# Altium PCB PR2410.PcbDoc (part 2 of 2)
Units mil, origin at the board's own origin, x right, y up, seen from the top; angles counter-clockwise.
Board outline 2750 x 3900 mil, 2 copper layers (Top Layer, Bottom Layer), stack 61.6 mil thick; 140 components, 78 nets, 324 pads, 132 vias.
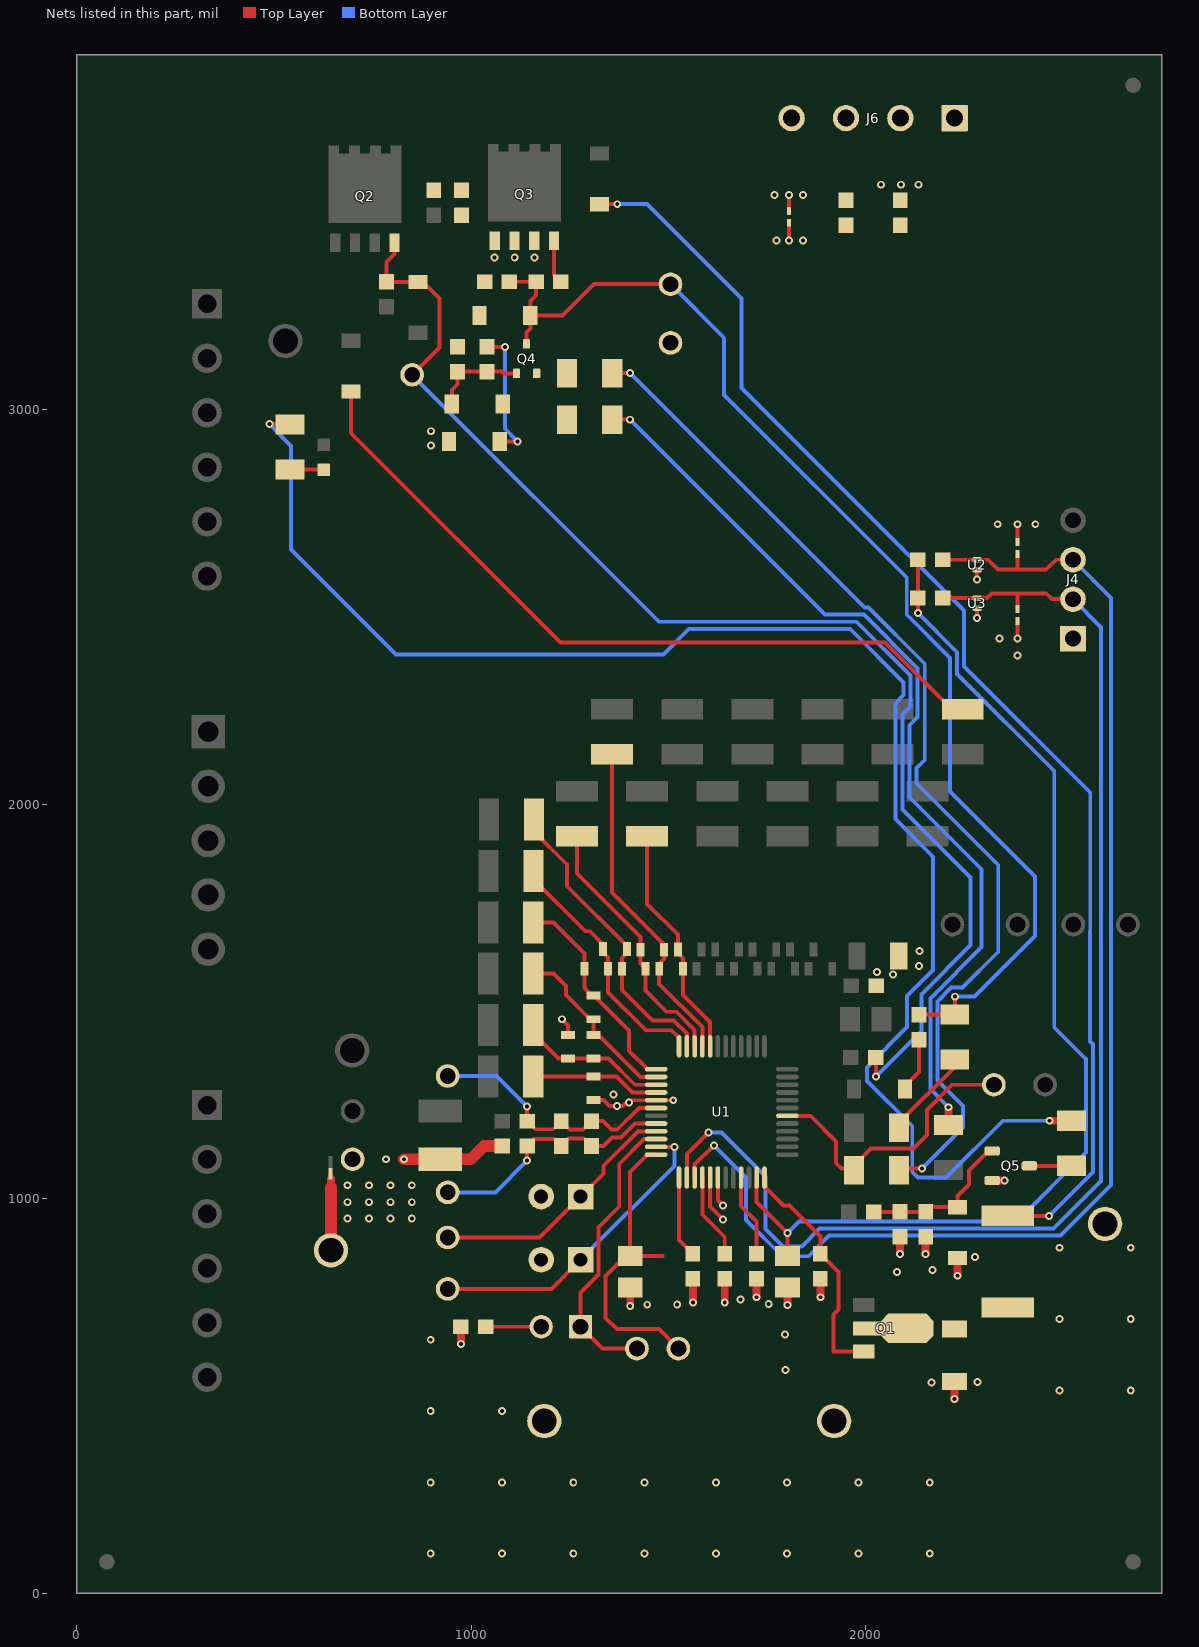
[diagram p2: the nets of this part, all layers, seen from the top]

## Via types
v1: diameter 20, hole 10, Top Layer to Bottom Layer, tented top, 132 vias

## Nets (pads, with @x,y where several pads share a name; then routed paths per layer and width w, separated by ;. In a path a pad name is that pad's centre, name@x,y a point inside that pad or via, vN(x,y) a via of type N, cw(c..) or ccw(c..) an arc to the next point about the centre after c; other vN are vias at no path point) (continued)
NetC11_2: C11.2 C12.1 R11.2 U1.8 | length 598.8
  Top Layer w10: R11.2@1445.82,1919 1445.82,1747.18 1523.67,1669.33 C11.2@1523.67,1632.08 1523.67,1622.33 1536.33,1609.67 C12.1@1536.33,1583.08 1536.33,1516.67 1605.47,1447.53 U1.8@1605.47,1386.34
NetC12_2: C12.2 C14.1 R12.2 U1.9 | length 846
  Top Layer w10: R12.2@1356.91,2127 1356.91,1776.09 1489,1644 C14.1@1489,1631.08 1489,1608 1476.33,1595.33 C12.2@1476.33,1583.08 1476.33,1544.56 1585.79,1435.11 U1.9@1585.79,1386.34
NetC13_1: C13.1 Q1.2 Q1.4 R9.1
NetC14_2: C14.2 C17.1 R13.2 U1.10 | length 670.8
  Top Layer w10: R13.2@1268,1919 1268,1824 1429,1663 C14.2@1429,1631.08 1429,1595.75 C17.1@1441.67,1583.08 1441.67,1527.33 1495,1474 1520,1474 1566.1,1427.9 U1.10@1566.1,1386.34
NetC17_2: C17.2 C18.1 R14.2 U1.11 | length 777.3
  Top Layer w10: R14.2@1159,1961 1159,1931 1242,1848 1242,1793 1394.33,1640.67 C18.1@1394.33,1633.08 1394.33,1622.71 1381.67,1610.04 C17.2@1381.67,1583.08 1381.67,1529.33 1458.91,1452.09 1512.91,1452.09 1546.42,1418.58 U1.11@1546.42,1386.34
NetC18_2: C18.2 C19.1 R16.2 U1.12 | length 642.6
  Top Layer w10: R16.2@1158,1830.8 1158,1809 1289,1678 1301,1678 1334.33,1644.67 C18.2@1334.33,1633.08 1334.33,1624.67 1347,1612 C19.1@1347,1583.08 1347,1522.51 1442.51,1427 1508,1427 1526.73,1408.27 U1.12@1526.73,1386.34
NetC19_2: C19.2 C20.1 R17.2 U1.13 | length 547.4
  Top Layer w10: R17.2@1157.09,1700.6 1208.4,1700.6 1287,1622 C19.2@1287,1583.08 1287,1534 1306,1515 C20.1@1310,1515 1311,1515 1400,1426 1400,1374.67 1446.4,1328.27 U1.13@1468.66,1328.27
NetC20_2: C20.2 C21.1 R18.2 U1.14 | length 456.9
  Top Layer w10: R18.2@1157.09,1570.4 1208.6,1570.4 1240,1539 1240,1516 1301,1455 C20.2@1310,1455 C21.1@1310,1415 1322,1415 1428.42,1308.58 U1.14@1468.66,1308.58
NetC21_2: C21.2 C23.1 R19.2 U1.15 | length 386.7
  Top Layer w10: R19.2@1157.09,1440.2 1157.09,1418.91 1221,1355 C23.1@1245,1355 C21.2@1310,1355 1348.28,1355 1414.38,1288.9 U1.15@1468.66,1288.9
NetC22_1: C22.1 R21.2 U1.16 | length 328.5
  Top Layer w10: R21.2@1157.09,1310 C22.1@1310,1310 1368,1310 1408.79,1269.21 U1.16@1468.66,1269.21
NetC28_1: C28.1 C29.2
NetC30_1: C30.1 C31.2
NetC32_2: C32.2 D9.1 Q5.1 R36.1 R38.2 | length 401.7
  Top Layer w10: R36.1@2020,966.22 C32.2@2087,966.22 R38.2@2151.96,966.22 2164.2,978.47 D9.1@2233,978.47 2233,1007 2262,1036 2262,1071 2311.75,1120.75 Q5.1@2320.51,1120.75
NetD1_1: D1.1 R1.2 | length 1946.5
  Top Layer w10: D1.1@695,3046.53 695,2940.83 1225.83,2410 2049,2410 2217.83,2241.17 R1.2@2246,2241.17
NetD2_1: D2.1 R9.2 | length 3304.9
  Top Layer w10: D2.1@1325,3521.56 v1(1370,3521.56) ; R9.2@2360,956.5 v1(2464.85,956.5)
  Bottom Layer w10: v1(1370,3521.56) 1445.44,3521.56 1685,3282 1685,3055.54 2249.62,2490.91 2249.62,2349.38 2569.37,2029.63 2569.37,1677.24 2569,1676.87 2569,1398.71 2575.87,1391.84 2575.87,1067.51 v1(2464.85,956.5)
NetD4_1: D4.1 R29.2 | length 86
  Top Layer w10: R29.2@540,2848.5 D4.1@626,2848.5
NetD5_1: D5.1 Q2.4 R31.2 R37.2 TP17.1 | length 3297.2
  Top Layer w10: Q2.4@805,3424.45 805,3395 785,3375 R31.2@785,3324.47 D5.1@865,3324.47 877.32,3324.47 919,3282.78 919,3158 TP17.1@850,3089 ; v1(2026.38,1310) 2026.38,1349.68 R37.2@2026.69,1350
  Bottom Layer w10: TP17.1@850,3089 1476.13,2462.87 1977.13,2462.87 2113.93,2326.07 2113.93,2247.93 2093.47,2227.47 2093.47,1986.53 2266,1814 2266,1643 2141,1518 2141,1424.62 v1(2026.38,1310)
NetD6_1: D6.1 Q4.3 R32.2 R34.2 R39.2 R40.2 TP18.1 | length 3062.2
  Top Layer w10: R32.2@1096.5,3325 R34.2@1164.04,3325 1164.04,3290.51 1149.47,3275.94 D6.1@1149.47,3238.98 ; Q4.3@1140,3167.4 1140,3196.48 1149.47,3205.94 D6.1@1149.47,3238.98 ; TP18.1@1505,3318.7 1310.83,3318.7 1231.1,3238.98 D6.1@1149.47,3238.98 ; R40.2@2135,1466.5 2135.59,1467.09 R39.2@2226.02,1467.09 v1(2226.02,1512.09)
  Bottom Layer w10: TP18.1@1505,3318.7 1640.69,3183.01 1640.69,3038.22 2104,2574.9 2104,2480.92 2213.87,2371.04 2213.87,2032.13 2429,1817 2429,1665.71 2275.38,1512.09 v1(2226.02,1512.09)
NetD7_1: D7.1 Q4.1 R33.2 R35.1 | length 239
  Top Layer w10: D7.1@950.53,3015 950.53,3050.53 965,3065 R33.2@965,3096.87 R35.1@1040,3096.87 1078.13,3096.87 1082.4,3092.6 Q4.1@1114.41,3092.6
NetD8_1: D8.1 R35.2 | length 343.2
  Top Layer w10: R35.2@1040,3159.86 v1(1085,3159.86) ; D8.1@1072.2,2920 v1(1117.2,2920)
  Bottom Layer w10: v1(1085,3159.86) 1085,2952.2 v1(1117.2,2920)
NetD10_2: D10.2 R40.1 | length 143.7
  Top Layer w10: D10.2@2099.47,1274.57 D10.2@2099.47,1278.57 2099.47,1285.47 2135,1321 R40.1@2135,1403.5
NetE1_1: E1.1 J4.3 R23.2 U1.27 U2.1 | length 3382.5
  Top Layer w10: U1.27@1566.1,1053.66 1566.1,1086.1 v1(1615,1135) ; R23.2@2191.81,2620 R23.2@2195.26,2620 U2.1@2282.52,2620 2310,2620 2335,2595 2385,2595 ; E1.1@2385,2635 2385,2595 ; J4.3@2525.59,2620 2482,2620 2457,2595 2385,2595
  Bottom Layer w10: v1(1615,1135) 1696,1054 1696,946.35 1788.36,854 1855,854 1907.38,906.38 2493.38,906.38 2622.08,1035.08 2622.08,2523.51 J4.3@2525.59,2620
NetE2_1: E2.1 J4.2 R24.2 U1.26 U3.1 | length 3288.9
  Top Layer w10: U1.26@1546.42,1053.66 1546.42,1113.42 v1(1601,1168) ; R24.2@2191.81,2522.8 U3.1@2282.52,2522.8 2307.8,2522.8 2320,2535 2385,2535 ; E2.1@2385,2495 2385,2535 ; J4.2@2525.59,2520 2472.8,2520 2457.8,2535 2385,2535
  Bottom Layer w10: v1(1601,1168) 1634,1168 1746,1056 1746,923.07 1790.07,879 1838,879 1883.25,924.25 2476.25,924.25 2597,1045 2597,2448.59 J4.2@2525.59,2520
NetJ5_1: J5.1 TP12.1 U1.22 | length 739.1
  Top Layer w10: TP12.1@1420,620 1332.28,620 J5.1@1277,675.28 1277,762.07 1322.37,807.44 1322.37,927.37 1375,980 1375,1088.19 1437.92,1151.1 U1.22@1468.66,1151.1
NetJ5_2: J5.2 R27.2 | length 140.5
  Top Layer w10: R27.2@1036.5,675.28 J5.2@1177,675.28
NetQ3_4: Q3.4 R34.1 | length 111
  Top Layer w10: Q3.4@1209.45,3428.74 1209.45,3342.58 R34.1@1227.03,3325
NetQ5_3: Q5.3 R30.1 | length 107
  Top Layer w10: Q5.3@2415,1083.35 R30.1@2522,1083.35
NetR15_2: R15.2 U1.33 | length 209.9
  Top Layer w10: U1.33@1684.21,1053.66 1684.21,980.79 1723.36,941.65 R15.2@1723.36,860
NetR20_2: R20.2 U1.28 | length 217.2
  Top Layer w10: U1.28@1585.79,1053.66 1585.79,959.21 1642.53,902.47 R20.2@1642.53,860
NetR22_2: R22.2 U1.25 | length 208.2
  Top Layer w10: U1.25@1526.73,1053.66 1526.73,894.98 R22.2@1561.71,860
NetR29_1: R29.1 R30.2 | length 4016
  Top Layer w10: v1(488,2964) 538.67,2964 R29.1@540,2962.67
  Top Layer w20: v1(2466.14,1197.52) R30.2@2522,1197.52
  Bottom Layer w10: v1(488,2964) 543,2909 543,2646 809,2380 1487,2380 1552,2445 1960.18,2445 2096.06,2309.13 2096.06,2276.63 2075.59,2256.17 2075.59,1962.41 2171,1867 2171,1580 2105,1514 2105,1435 2003.12,1333.12 2003.12,1298.88 2118,1184 2118,1068 2132.87,1053.13 2203.61,1053.13 2348.01,1197.52 v1(2466.14,1197.52)
NetR39_1: R39.1 R41.2 | length 227.7
  Top Layer w10: R41.2@2084.71,1183.7 2084.71,1192.7 2226.02,1334.02 R39.1@2226.02,1352.91
NetR42_1: R42.1 R43.2 | length 2680.8
  Top Layer w10: R43.2@1357.09,3093.27 v1(1402.09,3093.27) ; R42.1@2084.71,1076 v1(2142.5,1076)
  Bottom Layer w10: v1(1402.09,3093.27) 1996.73,2498.62 2007.45,2498.62 2149.68,2356.4 2149.68,2112.18 2129.22,2091.72 2129.22,2053.31 2336,1846.53 2336,1626 2244.96,1534.96 2216.55,1534.96 2182,1500.41 2182,1300.1 2247,1235.1 2247,1180.5 v1(2142.5,1076)
NetR44_1: R44.1 R45.2 | length 2350.5
  Top Layer w10: R45.2@1357.09,2975.16 v1(1402.09,2975.16)
  Top Layer w20: R44.1@2210,1186.85 v1(2210,1231.85)
  Bottom Layer w10: v1(1402.09,2975.16) 1896.5,2480.75 1995.25,2480.75 2131.8,2344.2 2131.8,2220.78 2111.34,2200.32 2111.34,2017.9 2294,1835.24 2294,1637.69 2164,1507.69 2164,1277.85 v1(2210,1231.85)
NetRT1_1: RT1.1 TP4.1 U1.21 | length 652.1
  Top Layer w10: TP4.1@940,901.5 1173.22,901.5 RT1.1@1277,1005.28 1334.96,1063.24 1334.96,1083.47 1422.28,1170.79 U1.21@1468.66,1170.79
NetRT2_1: RT2.1 TP6.1 U1.23 | length 798.2
  Top Layer w10: TP6.1@940,771.18 1202.9,771.18 RT2.1@1277,845.28 ; U1.23@1468.66,1131.42 1469.57,1130.51 v1(1515,1130.51)
  Bottom Layer w10: RT2.1@1277,845.28 1515,1083.28 v1(1515,1130.51)
PACK: R42.2 TP21.1 U1.42 | length 742.2
  Top Layer w10: U1.42@1801.34,1210.16 1859.84,1210.16 1925,1145 1925,1089.86 1938.86,1076 1970.53,1076 1970.53,1084.53 2013.42,1127.42 2121.42,1127.42 2155,1161 2155,1225 2218.9,1288.9 TP21.1@2325,1288.9
PACK+: C29.1 C30.2 D6.2 D7.2 E3.1 J6.3 J6.4 Q3.1 Q3.2 Q3.3 Q4.2 R32.1 R33.1 R43.1 R45.1 TP16.1 | length 40
  Top Layer w10: E3.1@1805,3504.45 v1(1805,3544.45)
  other v1: 1059,3386 1110,3386 1160,3386 1769,3544.45 1841,3544.45
PGND: C31.1 D8.2 E1.2 E2.2 E3.2 J4.1 J6.1 J6.2 R26.1 R28.1 TP20.1 U2.2 U3.2 | length 447.2
  Top Layer w10: v1(1805,3429.45) E3.2@1805,3474.45 ; v1(2282.52,2472.8) U3.2@2282.52,2497.21 ; v1(2282.52,2570) U2.2@2282.52,2594.41 ; v1(2385,2420) E2.2@2385,2465 ; E1.2@2385,2665 v1(2385,2710)
  Top Layer w30: v1(829,1099.98) R28.1@921,1099.98 997.98,1099.98 1031.51,1133.5 R26.1@1078.5,1133.5
  other v1: 686,950 740.33,950 794.67,950 849,950 686,991 740.33,991 794.67,991 849,991 686,1034 740.33,1034 794.67,1034 849,1034 784,1099.98 2385,2377 2339,2420 2334.68,2710 2430,2710 898,2910 898,2946 1774,3429.45 1841,3430 2038.68,3571 2089,3571 2134,3571
REG1: C15.2 R23.1 R24.1 U1.35 | length 2751.5
  Top Layer w10: U1.35@1723.58,1053.66 1723.58,991.42 v1(1801.91,913.09) C15.2@1801.91,854.49 ; v1(2132.26,2485) R24.1@2132.26,2522.8 R23.1@2132.26,2620
  Bottom Layer w10: v1(1801.91,913.09) 1830.95,942.13 2383.13,942.13 2557.99,1116.99 2557.99,1354.01 2478,1434 2478,2084 2231.75,2330.25 2231.75,2385.52 v1(2132.26,2485)
REG18: C24.2 TP7.1 U1.24 | length 786.5
  Top Layer w10: U1.24@1468.66,1111.73 1447.01,1111.73 1402.8,1067.52 C24.2@1402.8,854.49 ; 1485.31,854.49 C24.2@1402.8,854.49 ; TP7.1@1525,620 1476,669 1369,669 1340.25,697.75 1340.25,804.25 1390.49,854.49 C24.2@1402.8,854.49
REGIN: C16.2 Q1.3 U1.36 | length 610.2
  Top Layer w10: U1.36@1743.27,1053.66 1743.27,1030.73 1791.21,982.8 1806.21,982.8 1885,904 C16.2@1885,860 1930.67,814.33 1930.67,718.67 1918,706 1918,612.29 Q1.3@1995.2,612.29
SRN: C26.2 C27.2 R26.2 TP14.1 U1.20 | length 652.5
  Top Layer w10: v1(1141.5,1096.5) R26.2@1141.5,1133.5 1159.09,1151.1 1210.4,1151.1 C27.2@1228,1133.5 1246.5,1152 1285,1152 1303.5,1133.5 1335.51,1133.5 1357,1155 1379.88,1155 1415.36,1190.47 U1.20@1468.66,1190.47
  Bottom Layer w10: TP14.1@940,1016 1061,1016 v1(1141.5,1096.5)
SRP: C26.1 C27.1 R25.2 TP13.1 U1.18 | length 664.2
  Top Layer w10: v1(1141.5,1233.5) R25.2@1141.5,1196.5 1161.99,1176 1207.5,1176 C27.1@1228,1196.5 1249.5,1175 1283.5,1175 C26.1@1305,1196.5 1333.5,1196.5 1355,1175 1370,1175 1424.84,1229.84 U1.18@1468.66,1229.84
  Bottom Layer w10: TP13.1@940,1311 1064,1311 v1(1141.5,1233.5)
VSS: C1.2 C2.2 C13.2 C15.1 C16.1 C22.2 C23.2 C24.1 C32.1 D9.2 NT1.1 Q5.2 R15.1 R20.1 R22.1 R27.1 R38.1 RT1.2 RT2.2 TP8.1 TP9.1 TP10.1 TP11.1 U1.17 U1.29 U1.30 | length 1209.4
  Top Layer w10: NT1.1@643,1052 NT1.1@643,1063 ; v1(1229.51,1455) 1245,1439.51 C23.2@1245,1415 ; C22.2@1310,1250 1335,1250 1350,1235 v1(1369,1235) 1384.8,1235 1393.8,1244 v1(1399.33,1244) 1399.33,1249.53 U1.17@1468.66,1249.53 v1(1512,1249.53) ; U1.29@1605.47,1053.66 1605.47,980.26 v1(1638.22,947.52) ; U1.30@1625.16,1053.66 1625.16,995.85 v1(1638.22,982.8)
  Top Layer w20: 644,1028 NT1.1@644,1051 ; v1(973.5,631.42) R27.1@973.5,675.28 ; v1(1402.8,727.56) C24.1@1402.8,774.49 ; v1(1561.71,737.16) R22.1@1561.71,797.01 ; v1(1642.53,737.16) R20.1@1642.53,797.01 ; v1(1723.36,750) R15.1@1723.36,797.01 ; v1(1801.91,730) C15.1@1801.91,774.49 ; v1(1885,750) C16.1@1885,797.01 ; v1(2087,859.37) C32.1@2087,903.23 ; v1(2151.96,859.37) R38.1@2151.96,903.23 ; v1(2225,492.21) C13.2@2225,536.07 ; v1(2233,804.53) D9.2@2233,849.53 ; Q5.2@2320.51,1045.94 v1(2351.5,1045.94)
  Top Layer w30: TP8.1@644,869 644,1028
  other v1: 897,100 1077.77,100 1258.54,100 1439.31,100 1620.08,100 1800.84,100 1981.61,100 2162.38,100 897,280.77 1077.77,280.77 1258.54,280.77 1439.31,280.77 1620.08,280.77 1800.84,280.77 1981.61,280.77 2162.38,280.77 897,461.54 1077.77,461.54 2491.23,514 2672,514 2167,534 2283,535 1797,566 897,642.31 1795,656 2491.23,694.77 2672,694.77 1446,731.09 1522,732 1754,732.53 1682,744 2079,814 2169,819.49 2277,852 2491.23,875.54 2672,875.54 1360,1264 2069,1568 2029,1575 2135,1590 2136,1628
pads on no net: FID1.1 FID2.1 FID3.1 H1.0 H2.0 H3.0 H4.0 J4.4 SH-J1.0 U1.19 U1.31 U1.32 U1.34 U1.39 U1.40 U1.44 U2.1S U2.2S U3.1S U3.2S
copper on no net: | length 147.6
  Top Layer w20: v1(1485.31,731.64) 1485.31,791.49 ; v1(1750.21,612.29) 1794.06,612.29 ; v1(2123.47,776.14) 2123.47,820

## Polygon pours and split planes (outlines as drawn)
VSS on Top Layer "TOP_LAYER_VSS_P624" (solid, remove dead copper, pour order 624): 2267.02,1018.02 2267.02,950.46 2199.46,950.46 2183.73,934.73 2065.73,934.73 2048,917 2048,850 2021,823 1466,823 1451.09,808.09 1367.85,808.09 1357.76,798 1357.76,627.76 1335,605 1076,605 1035,646 1035,679 1005,709 777,709 732,664 732,144 876,0 2492,0 2750,258 2750,1001 2675,1076 2291,1076 2277,1062 2277,1028
16P on Top Layer "TOP_LAYER_16P_P623" (solid, remove dead copper, pour order 623): 776.86,3462.14 785,3454 785,3323.49 813.7,3294.78 885.68,3294.78 903.93,3276.54 903.93,3148.93 645,2890 169,2890 -18,3077 -18,3870 13,3901 675,3901 720,3856 720,3519
BAT- on Top Layer "TOP_LAYER_BAT-_P621" (solid, remove dead copper, pour order 621): 432,867 404,839 404,711 321,628 274,628 213,567 213,486 249,450 557,450 590,483 590,897 616,923 616,1122 628.5,1134.5 649.5,1134.5 685.79,1170.79 961.79,1170.79 976,1185 976,1243.5 986.5,1254 1072,1254 1081,1263 1081,1356 1070,1367 1018,1367 927,1458 570,1458 432,1320
PACK+ on Top Layer "TOP_LAYER_PACK+_P622" (solid, remove dead copper, pour order 622): 1433,3321.24 1433,3822.24 1465,3854.24 1528,3854.24 1969,3854.24 1994,3829.24 1994,3530.7 1972.54,3509.24 1909,3509.24 1889,3529.24 1750.02,3529.24 1744,3523.22 1744,3403.24 1770,3377.24 1846,3377.24 1864,3359.24 1864,2857.56 1852.68,2846.24 1020,2846.24 1002,2864.24 1002,3033.24 1018,3049.24 1130.45,3049.24 1149,3067.79 1149,3118.65 1351.59,3321.24
PGND on Top Layer "TOP_LAYER_PGND_P609" (solid, remove dead copper, pour order 609): 963,2971 873,2971 856,2954 856,2875 874,2857 959,2857 974,2872 974,2960
VSS on Top Layer "TOP_LAYER_VSS_P612" (solid, remove dead copper, pour order 612): 1997,1521.3 2010.3,1508 2053,1508 2107,1562 2132,1562 2154,1584 2154,1638 2133,1659 2038,1659 1997,1618
VSS on Top Layer "TOP_LAYER_VSS_P607" (solid, remove dead copper, pour order 607): 1422,1248.2 1393.8,1220 1343.35,1220 1333.5,1229.84 1293.16,1229.84 1284,1239 1284,1268 1302,1286 1364,1286 1387,1263 1413,1263 1422,1254
PGND on Top Layer "TOP_LAYER_PGND_P618" (solid, remove dead copper, pour order 618): 969,1139 689,1139 663,1113 663,947.52 673.52,937 941,937 990,986 990,1118
16P on Top Layer "TOP_LAYER_16P_P610" (solid, remove dead copper, pour order 610): 929,3364 920,3355 837,3355 826,3366 826,3452 835,3461 867,3461 881,3475 881,3513 887,3519 924.71,3519 929,3514.71
NetC28_1 on Top Layer "TOP_LAYER_NETC28_1_P613" (solid, remove dead copper, pour order 613): 995,3534 1000,3539 1000,3678 991,3687 886,3687 876,3677 876,3543 885,3534
NetC30_1 on Top Layer "TOP_LAYER_NETC30_1_P616" (solid, remove dead copper, pour order 616): 1892,3489 1884,3481 1884,3315 1891,3308 2136,3308 2148,3320 2148,3483 2142,3489
NetC13_1 on Top Layer "TOP_LAYER_NETC13_1_P615" (solid, remove dead copper, pour order 615): 1969,690 2038,690 2068,720 2223,720 2264,761 2424,761 2437,748 2437,689 2420,672 2284,672 2239,627 2064,627 2039,652 1967,652 1965,654 1965,686
PGND on Top Layer "TOP_LAYER_PGND_P608" (solid, remove dead copper, pour order 608): 1820,3514.71 1854.74,3514.71 1859.88,3509.57 1859.88,3409.88 1850,3399.45 1773.55,3399.45 1760.29,3412.71 1760.29,3514.71 1790,3514.71 1790,3484.45 1820,3484.45
PGND on Top Layer "TOP_LAYER_PGND_P611" (solid, remove dead copper, pour order 611): 2400,2505 2435.32,2505 2455,2485.32 2455,2375 2440,2360 2333.9,2360 2315,2378.9 2315,2491.5 2328.5,2505 2370,2505 2370,2455 2400,2455
PGND on Top Layer "TOP_LAYER_PGND_P614" (solid, remove dead copper, pour order 614): 2370,2625 2334.68,2625 2315,2644.68 2315,2755 2330,2770 2450,2770 2460,2760 2460,2643.5 2441.5,2625 2400,2625 2400,2675 2370,2675
PACK+ on Top Layer "TOP_LAYER_PACK+_P617" (solid, remove dead copper, pour order 617): 1184,3375 1165.52,3356.52 1110.97,3356.52 1098.02,3343.57 1098.02,3205.02 1091,3198 1056.52,3198 1008.04,3198 1006.52,3196.48 1006.52,3134.96 943.08,3134.96 943.08,3517.07 946.52,3520.52 992.52,3520.52 996.52,3516.52 996.52,3480.97 1021.52,3455.97 1170.58,3455.97 1184,3442.54
no net on Top Layer "TOP_LAYER_NONET_P605" (solid, remove dead copper, pour order 605): 1114.41,3092.6
CD on Top Layer "TOP_LAYER_CD_P620" (solid, remove dead copper, pour order 620): 541,3879 1357.55,3879 1390,3846.55 1390,3575.55 1385,3570.55 1285.57,3570.55 1275,3559.98 1275,3494.55 1255,3474.55 1030,3474.55 1015,3489.55 1015,3579.55 1015,3683.55 1001,3697.55 879,3697.55 860,3678.55 860,3484.55 850,3474.55 576.41,3474.55 541,3511
no net on Top Layer "TOP_LAYER_NONET_P606" (solid, remove dead copper, pour order 606): 1365,3625
PGND on Top Layer "TOP_LAYER_PGND_P619" (solid, remove dead copper, pour order 619): 2270,3855 2035,3855 2010,3830 2010,3525 2025,3510 2275,3510 2305,3540 2305,3820
PGND on Bottom Layer "BOTTOM_LAYER_PGND_P628" (solid, remove dead copper, pour order 628): 869,1399 869,1976 1240,2347 2735,2347 2735,3900 12,3900 12,749 797.65,749 869,820.34
VSS on Bottom Layer "BOTTOM_LAYER_VSS_P627" (solid, remove dead copper, pour order 627): 890,1478 890,1985.34 1221.66,2317 2735,2317 2735,0 14,0 14,733 375,733 558,916 882,916 890,924
16P on Bottom Layer "BOTTOM_LAYER_16P_P625" (solid, remove dead copper, pour order 625): 641.51,3369.39 641.51,3430.74 679.35,3468.57 913.82,3468.57 923.35,3459.04 923.35,3380.25 898.84,3355.74 655.16,3355.74
PACK+ on Bottom Layer "BOTTOM_LAYER_PACK+_P626" (solid, remove dead copper, pour order 626): 1169.5,3676 1052.5,3676 1009.5,3633 1009.5,3385.87 1046.77,3348.6 1268.1,3348.6 1293.5,3374 1293.5,3553 1292.5,3554 1318.5,3580 1537.5,3580 1596.5,3521 1642.5,3475 1853.5,3475 1869.5,3491 1869.5,3601 1853.5,3617 1743.5,3617 1684.5,3676

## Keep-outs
Keep-Out Layer:
  the board outline again, w40
  text ".Layer_Name" at -323,-1258.49 h60

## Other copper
Top Layer:
  text "1" at 571.49,75.89 h50
  text ".Layer_Name" at -323,-1258.49 h60
Bottom Layer:
  text "2" at 596.48,75.06 h50
  text ".Layer_Name" at -323,-1258.49 h60

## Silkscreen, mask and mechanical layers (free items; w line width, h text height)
Top Overlay:
  rectangle: 2204,3581 2262,3600
  lines w10: 827,2991 827,2999 914,3086 922,3086 ; 2168,863 2168,831.73 2188.28,811.45
  text "J6" at 2322,3434 h30
  text "4.PACK+" at 2430.38,3347.42 h30 r90
  text "3.PACK+" at 2484.26,3347.42 h30 r90
  text "2.PACK-" at 2538.13,3347.42 h30 r90
  text "1.PACK-" at 2592,3347.42 h30 r90
  text "BAT+" at 425,3329 h40
  text "PACK+" at 1584,3064.6 h30 r90
  text "BAT+" at 477,3054 h30
  text "11" at 462,2548 h40
  text "10" at 457,2169 h40
  text "BAT" at 2181.47,1620.37 h30
  text "CP1" at 2351.5,1620 h30
  text "DSG" at 2632.74,1616 h30
  text "CHG" at 2485.47,1614.7 h30
  text "6" at 457,1601 h40
  text "BAT-" at 660,1521.62 h30
  text "PACK" at 2290,1381 h30
  text "LD" at 2436.77,1379.45 h30
  text "SRP" at 808.51,1293 h30
  text "5" at 453,1215 h40
  text "BAT-" at 601.58,1187.71 h30 r90
  text "PGND" at 600.58,1034.63 h30 r90
  text "SRN" at 794.67,950 h30
  text "TS1" at 806,842 h30
  text "VSS" at 2564,772 h30
  text "TS3" at 816,724.64 h30
  text "VSS" at 599.49,700 h30
  text "BAT-" at 453,527 h40
  text "TS2" at 1362,491 h30
  text "REG18" at 1495.3,487 h30
  text "VSS" at 1882,266 h30
  text "VSS" at 1148,264 h30
  text ".Layer_Name" at -323,-1258.49 h60
Top Paste:
  text ".Layer_Name" at -323,-1258.49 h60
Top Solder:
  text ".Layer_Name" at -323,-1258.49 h60
  text ".Layer_Name" at -323,-1258.49 h60
Bottom Solder:
  text ".Layer_Name" at -323,-1258.49 h60
Drill Guide:
  text ".Layer_Name" at -323,-1258.49 h60
M1 Board Outline:
  the board outline again, w10
M2 Board Dimensions:
  rectangle: 10,-465 135,-340
  rectangle: 135,-590 510,-465
  lines w7: 10,-465 1010,-465 ; 135,-590 135,-340 ; 260,-590 260,-340 ; 510,-590 510,-340 ; 760,-590 760,-340 ; 10,-590 1010,-590 1010,-340 10,-340 10,-590
M3 3D STEP Top:
  text ".Layer_Name" at -323,-1258.49 h60
M4 3D STEP Bottom:
  text ".Layer_Name" at -323,-1258.49 h60
M5 Assembly Top:
  rectangle: 2204,3581 2262,3600
  rectangle: 380,1174.79 414,1274.79
  rectangle: 380,3206 414,3306
  lines w10: -1192,-1330.17 5408,-1330.17 ; -1192,-1126.83 5410,-1126.83 ; -1192,-923.5 -1192,-1533.5 2813,-1533.5 5410,-1533.5 5410,-923.5 -1191.5,-923.5 -1191.5,-1533.5 384,-1533.5 ; 1273,-1533.5 1273,-923.5 ; 3336,-1330.17 3336,-1126.83 ; 4002,-1540 4002,-1337.17 ; 4040,-1126.83 4040,-923.5
  text "Assemble shunt part (SH-J1) on pins of J5." at -596,4193 h40
  text "COMPONENTS MARKED 'DNP' SHOULD NOT BE POPULATED." at 253.5,-718.5 h60
  text "ASSEMBLY VARIANT:" at 253,-834 h60
  text ".VariantName" at 1289,-834 h60
  text "PCB VIEWED FROM TOP SIDE" at -1128.5,-1055.67 h60
  text "BOARD #:" at 1348,-1055.67 h60
  text ".PRJ_TITLE" at 1893.5,-1055.67 h60
  text "REV:" at 4238,-1055.67 h60
  text ".PCB_Rev" at 4529.5,-1055.67 h60
  text ".VersionControl_RevNumber" at 4066,-1255 h60
  text "SVN REV:" at 3581,-1256 h60
  text "TID #:" at 1348,-1259 h60
  text ".TID" at 1893.5,-1259 h60
  text "TOP ASSEMBLY DRAWING" at -1129,-1261 h60
  text "GENERATED    :" at 1350,-1464.34 h60
  text ".Print_Date" at 2219.5,-1464.34 h60
  text ".Print_Time" at 2948.5,-1464.34 h60
  text "TEXAS INSTRUMENTS" at 4213,-1464.34 h60
M6 Assembly Bottom:
  lines w10: -1192.5,-1127.33 5409.5,-1127.33 ; -1190.5,-1330.67 5409.5,-1330.67 ; 215.5,-1540.5 215.5,-1337.67 ; 677.5,-1127.33 677.5,-924 ; 814,-1330.67 814,-1127.33 ; 2944.5,-1534 2944.5,-924 ; 3833.5,-1534 5409,-1534 5409,-924 -1192.5,-924 -1192.5,-1534 1404.5,-1534 5409.5,-1534 5409.5,-924
  text "COMPONENTS MARKED 'DNP' SHOULD NOT BE POPULATED." at 5202,-718 h60
  text ".VariantName" at 4158,-834 h60
  text "ASSEMBLY VARIANT:" at 5197,-834 h60
  text ".PCB_Rev" at 188,-1056.17 h60
  text "REV:" at 479.5,-1056.17 h60
  text ".PRJ_tITLE" at 2324,-1056.17 h60
  text "BOARD #:" at 2869.5,-1056.17 h60
  text "PCB VIEWED FROM BOTTOM SIDE" at 5346,-1056.17 h60
  text ".TID" at 2324,-1259.5 h60
  text "TID #:" at 2869.5,-1259.5 h60
  text "BOTTOM ASSEMBLY DRAWING" at 5346.5,-1261.5 h60
  text ".VersionControl_RevNumber" at 162.5,-1268.17 h60
  text "SVN REV:" at 668.5,-1268.17 h60
  text "TEXAS INSTRUMENTS" at 4.5,-1464.84 h60
  text ".Print_Time" at 1269,-1464.84 h60
  text ".Print_Date" at 1998,-1464.84 h60
  text "GENERATED    :" at 2867.5,-1464.84 h60
M9 Title Sheet:
  drawing of 57 lines, arcs and shapes, not listed
  text "1" at -160.16,7636.5 h70
  text "2" at 2335.5,7636.5 h70
  text "3" at 4824.84,7636.5 h70
  text "4" at 7331.51,7636.5 h70
  text "5" at 9830.5,7636.5 h70
  text "6" at 12335.5,7636.5 h70
  text "A" at -1316.5,6493.5 h70
  text "A" at 13483.5,6493.5 h70
  text "B" at -1316.5,4113.5 h70
  text "B" at 13483.5,4113.5 h70
  text "C" at -1316.5,1738.5 h70
  text "C" at 13483.5,1738.5 h70
  text "PROJECT TITLE:" at 10443.5,-122.5 h45
  text ".PRJ_Title" at 10493.5,-255.83 h70
  text "DESIGNED FOR:" at 10443.5,-423.5 h45
  text ".PRJ_Customer" at 10493.5,-563.5 h70
  text "D" at -1316.5,-631.5 h70
  text "D" at 13483.5,-631.5 h70
  text "FILE NAME:" at 10443.5,-723.5 h45
  text ".PCB_File_Name_No_Path" at 10493.5,-843.5 h70
  text "Texas Instruments (TI) and/or its licensors do not warrant the accuracy or completeness of this specification" at 5474,-1005.34 h45
  text "ENGINEER:" at 10443.5,-1013.5 h45
  text "LAYOUT BY:" at 12006,-1014 h45
  text "or any information contained therein. TI and/or its licensors do not warrant that this design will meet" at 5429.01,-1118 h45
  text ".PRJ_Engineer" at 10493.5,-1168.49 h70
  text ".PCB_Layout" at 12020,-1172 h70
  text "the specifications, will be suitable for your application or fit for any particular purpose, or will operate in" at 5429.01,-1230.67 h45
  text "ALTIUM DESIGNER VERSION:" at 11948.5,-1323.5 h45
  text "an implementation. TI and/or its licensors do not warrant that the design is production worthy. You should" at 5429.01,-1343.33 h45
  text "completely validate and test your design implementation to confirm the system functionality for your application." at 5474,-1456 h45
  text ".print_Scale" at 10493.5,-1456.83 h70
  text ".Application_BuildNumber" at 11999,-1456.83 h70
  text "WO# : 308259-8257-D" at 12102.12,-1662.23 h70
  text "1" at -160.16,-1663.5 h70
  text "2" at 2335.5,-1663.5 h70
  text "3" at 4824.84,-1663.5 h70
  text "4" at 7331.51,-1663.5 h70
  text "5" at 9830.5,-1663.5 h70
  text "6" at 11471,-1670 h70
M10 Fab Notes:
  drawing of 191 lines, arcs and shapes, not listed
  text "FAB NOTES:" at -952.85,7110.18 h60
  text "1. BOARD SIZE -  2750MIL x 3900MIL." at -965.39,6909.64 h60
  text "2. VENDOR MAY ADJUST SOLDERMASK WHEREVER SOLDERMASK PADS ARE THE SAME SIZE (1:1) AS PER THE MANUFACTURING CAPABILITIES" at -974.87,6785.78 h60
  text "AND ALL OTHER SOLDER MASK PADS SHALL NOT BE MODIFIED, PROVIDED NO ADJACENT COPPER IS EXPOSED AND NO CONFLICT IS PRODUCED" at -804.11,6670.13 h60
  text "WITH ANY STATED \"VIA TENTING/COVERING\" REQUIREMENTS." at -860.82,6558.06 h60
  text "3. ALL VIAS ARE TENTED ON TOP SIDE UNLESS OTHERWISE SOLDERMASK IS OPENED IN GERBER." at -978.1,6428.75 h60
  text "DESIGN INFORMATION" at 11482.02,5956.17 h60
  text "10" at 11900,5830 h60
  text "MIN. TRACK WIDTH:" at 10837.46,5824.05 h60
  text "MIL" at 12088.46,5824.05 h60
  text "MIL" at 12103.46,5714.05 h60
  text "7.874" at 11795,5710 h60
  text "MIN. CLEARANCE:" at 10837.46,5699.92 h60
  text "MIN. VIA PAD SIZE:" at 10837.46,5575.8 h60
  text "20" at 11903.71,5575.8 h60
  text "MIL" at 12088.46,5575.8 h60
  text "0.05mm (2MIL)" at 11532.46,5445.9 h60
  text "MINIMUM ANNULAR RING" at 10508.23,5437.68 h60
  text "EXTERNAL" at 12240.46,5437.68 h60
  text "PER" at 10708.23,5327.55 h60
  text "IPC-D-275 CLASS 2 LEVEL C" at 10928.23,5327.54 h60
  text "MIL, HOLES" at 12416.46,5227.07 h60
  text "+/-" at 12024,5218.48 h60
  text "+/-" at 12878,5218.48 h60
  text "REGISTRATION TOLERANCES:" at 10508.23,5217.42 h60
  text "METAL" at 11708,5217.42 h60
  text "5" at 12284.2,5217.42 h60
  text "3" at 13117.2,5217.42 h60
  text "MIL" at 13233.46,5217.42 h60
  text "HOLE SIZE TOLERANCE (UNLESS OTHERWISE SPECIFIED):" at 10508.23,5119.1 h60
  text "+/-" at 12878,5116.23 h60
  text "3" at 13117.2,5115.17 h60
  text "MIL" at 13233.46,5115.17 h60
  text "MATERIAL:" at 10433.46,4977.52 h60
  text "FR-4 High Tg" at 11419.9,4849 h60
  text "X" at 11275.46,4841.01 h60
  text "FR-408" at 10854.46,4836.49 h60
  text "OTHER" at 12342.46,4836.49 h60
  text "62 MIL (1.6mm) +/-10%" at 11174.56,4693.46 h60
  text "X" at 11054.46,4691.01 h60
  text "THICKNESS:" at 10508.23,4685.24 h60
  text "OTHER" at 12459.46,4685.24 h60
  text "TOLERANCE:" at 10508.23,4546.92 h60
  text "X" at 11356.46,4546.92 h60
  text "ANSI IPC-6012 TYPE 3 CLASS 2" at 11534.48,4546.92 h60
  text "OTHER +/-" at 11534.46,4402.73 h60
  text "BOW & TWIST:" at 10508.23,4257.54 h60
  text "X" at 11356.46,4257.54 h60
  text "ANSI IPC-6012 TYPE 3 CLASS 2" at 11534.48,4257.54 h60
  text "OTHER +/-" at 11534.46,4110.85 h60
  text "DRILLING:" at 10433.46,3980.23 h60
  text "NC_DRILL FILES" at 12194.46,3875.04 h60
  text "REFERENCE:" at 10508.23,3871.1 h60
  text "X" at 11165.46,3871.01 h60
  text "AS SHOWN" at 11343.46,3871.1 h60
  text "X" at 12066.46,3871.1 h60
  text "OTHER" at 12492.46,3728.85 h60
  text "PTH COPPER THICKNESS:" at 10507.91,3725.32 h60
  text "X" at 11647.14,3725.32 h60
  text "20-30 um" at 11775.14,3725.32 h60
  text "BOARD FINISH:" at 10433.46,3577.73 h60
  text "SILKSCREEN:" at 10588.68,3467.6 h60
  text "X" at 11546.46,3467.6 h60
  text "TOP" at 11663.46,3467.6 h60
  text "BOTTOM" at 12174.46,3467.6 h60
  text "SILKSCREEN COLOR:" at 10588.68,3312.41 h60
  text "X" at 11545.46,3312.41 h60
  text "WHITE" at 11663.46,3312.41 h60
  text "OTHER" at 12174.46,3312.41 h60
  text "X" at 11676.46,3168.96 h60
  text "GREEN" at 11794.46,3168.96 h60
  text "OTHER" at 12412.46,3168.96 h60
  text "SOLDER RESIST COLOR:" at 10588.68,3162.1 h60
  text "MATTE" at 11794.46,3014.71 h60
  text "X" at 12264.46,3013.71 h60
  text "SEMI-GLOSS" at 12412,3014.07 h60
  text "IMMERSION GOLD (ENIG)" at 11494.46,2841.94 h60
  text "ENEPIG" at 12832,2834.72 h60
  text "SURFACE FINISH:" at 10433.46,2833.72 h60
  text "X" at 11316.46,2833.72 h60
  text "IMM. TIN/SILVER OR EQUIV" at 10763,2696.4 h60
  text "OTHER" at 12194.46,2692.47 h60
  text "ARRAY/PANEL:" at 10433.46,2537.09 h60
  text "CUT AND TRIM PER M1 BOARD OUTLINE" at 11494.46,2528.87 h60
  text "N.C. ROUTE" at 11494.46,2392.9 h60
  text "X" at 12182.46,2392.9 h60
  text "V. SCORE" at 12360.46,2392.9 h60
  text "CERTIFICATION:" at 10433.46,2263.77 h60
  text "MATERIALS AND WORKMANSHIP FOR ALL PCBS" at 11158.46,2263.77 h60
  text "TO MEET OR EXCEED THE REQUIREMENTS OF:" at 11158.46,2169.71 h60
  text "X" at 10795.97,2041.08 h60
  text "ANSI IPC-A-600F CLASS ->" at 10923.96,2041.08 h60
  text "X" at 12571.97,2041.08 h60
  text "2" at 12681.96,2041.08 h60
  text "1" at 12366.96,2039.58 h60
  text "3" at 13035.96,2039.58 h60
  text "X" at 11607.97,1893.39 h60
  text "RoHS" at 11735.96,1893.39 h60
  text "OTHER" at 12380.36,1893.39 h60
  text "PER ORDER" at 12777.42,1893.39 h60
  text "ALL BOARDS MUST MEET OR EXCEED UL94-V0 REQUIREMENTS." at 10461,1739.57 h60
  text "PCB MUST BEAR THE UL94V-0 UL REGISTERED MATERIAL ID NUMBER" at 10461,1623.5 h60
  text "ADDITIONAL REQUIREMENTS:" at 10433.46,1454.08 h60
  text "MICROSECTION:" at 10508.23,1346.95 h60
  text "YES" at 11413.96,1346.95 h60
  text "REQUIRED" at 12275.46,1202.62 h60
  text "BARE BOARD ELEC. TEST:" at 10508.23,1199.76 h60
  text "NONE" at 11813.96,1199.76 h60
  text "X" at 12157.46,1199.76 h60
  text "PER ORDER" at 12867.46,1199.76 h60
  text "XX MIL VIAS REQUIRE NON-CONDUCTIVE FILL AND PLANARIZE" at 10676.38,994.82 h59
  text "XX MIL VIAS REQUIRE CONDUCTIVE FILL AND PLANARIZE" at 10684.38,890.84 h60
  text "OUTER XX MIL TRACES REQUIRE 50 OHM SINGLE-ENDED IMPEDANCE" at 10683.39,727.46 h58
  text "LAYER 2 & 3 (INNER LAYERS) XX MIL WIDE, XX MIL SPACE / TRACES REQUIRE 100 OHM DIFFERENTIAL IMPEDANCE" at 10675.39,491.75 h60
M11 Gerber Information:
  lines w10: -1192,-1330.17 5408,-1330.17 ; -1192,-1126.83 5410,-1126.83 ; -1192,-923.5 -1192,-1533.5 2813,-1533.5 5410,-1533.5 5410,-923.5 -1191.5,-923.5 -1191.5,-1533.5 384,-1533.5 ; 1273,-1533.5 1273,-923.5 ; 3383,-1330.33 3383,-1127 ; 3540,-1126.83 3540,-923.5 ; 4002,-1540 4002,-1337.17
  text "ALL ARTWORK VIEWED FROM TOP SIDE" at -1128.5,-1055.67 h60
  text "BOARD #:" at 1348,-1055.67 h60
  text ".PRJ_Title" at 1893.5,-1055.67 h60
  text "REV:" at 3738,-1055.67 h60
  text ".PCB_Rev" at 4029.5,-1055.67 h60
  text "LAYER NAME =" at -1128.5,-1258.49 h60
  text "TID #:" at 1348,-1259 h60
  text ".TID" at 1893.5,-1259 h60
  text "SVN REV:" at 3467,-1268 h60
  text ".VersionControl_RevNumber" at 3960,-1268 h60
  text "GENERATED    :" at 1350,-1464.34 h60
  text ".Print_Date" at 2219.5,-1464.34 h60
  text ".Print_Time" at 2948.5,-1464.34 h60
  text "TEXAS INSTRUMENTS" at 4213,-1464.34 h60
M12 Stackup:
  drawing of 165 lines, arcs and shapes, not listed
  text "LAYER STACK-UP :" at 3854,1936 h60
  text "Layer" at 3917.34,1737 h60
  text "Name" at 4327.26,1737 h60
  text "Material" at 5187.02,1737 h60
  text "Thickness" at 6046.79,1737 h60
  text "Constant" at 6696.63,1737 h60
  text "Board Layer Stack" at 7266.49,1737 h60
  text "1" at 3917.34,1617 h60
  text "Top Overlay" at 4327.26,1617 h60
  text "2" at 3917.34,1497 h60
  text "Top Solder" at 4327.26,1497 h60
  text "Solder Resist" at 5187.02,1497 h60
  text "0.40mil" at 6046.79,1497 h60
  text "3.5" at 6696.63,1497 h60
  text "3" at 3917.34,1377 h60
  text "Top Layer" at 4327.26,1377 h60
  text "Copper" at 5187.02,1377 h60
  text "2.80mil" at 6046.79,1377 h60
  text "4" at 3917.34,1257 h60
  text "Dielectric" at 4327.26,1257 h60
  text "FR-4 High Tg" at 5187.02,1257 h60
  text "56.00mil" at 6046.79,1257 h60
  text "4.2" at 6696.63,1257 h60
  text "5" at 3917.34,1137 h60
  text "Bottom Layer" at 4327.26,1137 h60
  text "Copper" at 5187.02,1137 h60
  text "2.80mil" at 6046.79,1137 h60
  text "6" at 3917.34,1017 h60
  text "Bottom Solder" at 4327.26,1017 h60
  text "Solder Resist" at 5187.02,1017 h60
  text "0.40mil" at 6046.79,1017 h60
  text "3.5" at 6696.63,1017 h60
  text "NOTE:" at 3922,797 h60
  text "1. THIS IS A NON-IMPEDANCE CONTROLLED BOARD" at 4037.44,658.51 h60
  text "2. EXTERNAL LAYER CU THICKNESS ARE FINISHED THICKNESS AFTER PLATING." at 4025.41,483.87 h60
M13 Component Bodies Top:
  text ".Layer_Name" at -323,-1258.49 h60
M14 Component Bodies Bottom:
  text ".Layer_Name" at -323,-1258.49 h60
M15 Courtyards Top:
  text ".Layer_Name" at -323,-1258.49 h60
M16 Courtyards Bottom:
  text ".Layer_Name" at -323,-1258.49 h60
Drill Drawing:
  lines w15: 587.34,4532.5 5202.11,4532.5 ; 587.34,5732.5 5202.11,5732.5 ; 1138.22,4382.5 1138.22,5882.5 ; 1728.07,4382.5 1728.07,5882.5 ; 2827.75,4382.5 2827.75,5882.5 ; 3333.62,4382.5 3333.62,5882.5 ; 4067.42,4382.5 4067.42,5882.5 ; 587.34,4382.5 5202.11,4382.5 5202.11,5882.5 587.34,5882.5 587.34,4382.5
  text "DRILL CHART :" at 681,5945 h60
  text "Symbol" at 677.34,5777.5 h72
  text "Count" at 1183.22,5777.5 h72
  text "Hole Size" at 1773.07,5777.5 h72
  text "Plated" at 2872.75,5777.5 h72
  text "Hole Type" at 3378.62,5777.5 h72
  text "Hole Tolerance" at 4112.42,5777.5 h72
  text "132" at 1183.22,5627.5 h60
  text "10.00mil (0.254mm)" at 1773.07,5627.5 h60
  text "PTH" at 2872.75,5627.5 h60
  text "Round" at 3378.62,5627.5 h60
  text "+0.00mil/-10.00mil" at 4112.42,5627.5 h60
  text "A" at 648.26,5617.51 h66.67
  text "4" at 1183.22,5477.5 h60
  text "35.00mil (0.889mm)" at 1773.07,5477.5 h60
  text "PTH" at 2872.75,5477.5 h60
  text "Round" at 3378.62,5477.5 h60
  text "+/-3.00mil" at 4112.42,5477.5 h60
  text "B" at 648.26,5467.51 h66.67
  text "19" at 1183.22,5327.5 h60
  text "40.00mil (1.016mm)" at 1773.07,5327.5 h60
  text "PTH" at 2872.75,5327.5 h60
  text "Round" at 3378.62,5327.5 h60
  text "+/-3.00mil" at 4112.42,5327.5 h60
  text "C" at 648.26,5317.51 h66.67
  text "4" at 1183.22,5177.5 h60
  text "40.16mil (1.020mm)" at 1773.07,5177.5 h60
  text "PTH" at 2872.75,5177.5 h60
  text "Round" at 3378.62,5177.5 h60
  text "+/-3.00mil" at 4112.42,5177.5 h60
  text "D" at 648.26,5167.51 h66.67
  text "4" at 1183.22,5027.5 h60
  text "43.31mil (1.100mm)" at 1773.07,5027.5 h60
  text "PTH" at 2872.75,5027.5 h60
  text "Round" at 3378.62,5027.5 h60
  text "+/-3.00mil" at 4112.42,5027.5 h60
  text "E" at 648.26,5017.51 h66.67
  text "12" at 1183.22,4877.5 h60
  text "47.00mil (1.194mm)" at 1773.07,4877.5 h60
  text "PTH" at 2872.75,4877.5 h60
  text "Round" at 3378.62,4877.5 h60
  text "+/-3.00mil" at 4112.42,4877.5 h60
  text "F" at 648.26,4867.51 h66.67
  text "5" at 1183.22,4727.5 h60
  text "52.00mil (1.321mm)" at 1773.07,4727.5 h60
  text "PTH" at 2872.75,4727.5 h60
  text "Round" at 3378.62,4727.5 h60
  text "+/-3.00mil" at 4112.42,4727.5 h60
  text "G" at 648.26,4717.51 h66.67
  text "6" at 1183.22,4577.5 h60
  text "63.00mil (1.600mm)" at 1773.07,4577.5 h60
  text "PTH" at 2872.75,4577.5 h60
  text "Round" at 3378.62,4577.5 h60
  text "+/-3.00mil" at 4112.42,4577.5 h60
  text "H" at 648.26,4567.51 h66.67
  text "186 Total" at 1183.22,4427.5 h60
  text "FAB" at -323,-1258.49 h60
M17 Embedded Cavity:
  text ".Layer_Name" at -323,-1258.49 h60
M18 Embedded Assembly:
  text ".Layer_Name" at -323,-1258.49 h60
M19 Embedded Keepout:
  text ".Layer_Name" at -323,-1258.49 h60

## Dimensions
0,0 to 0,3900 on M2 Board Dimensions
0,0 to 2750,0 on M2 Board Dimensions
19,-14.01 to 198,-86.01 on M2 Board Dimensions
10,-590 to 1010,-590 on M2 Board Dimensions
